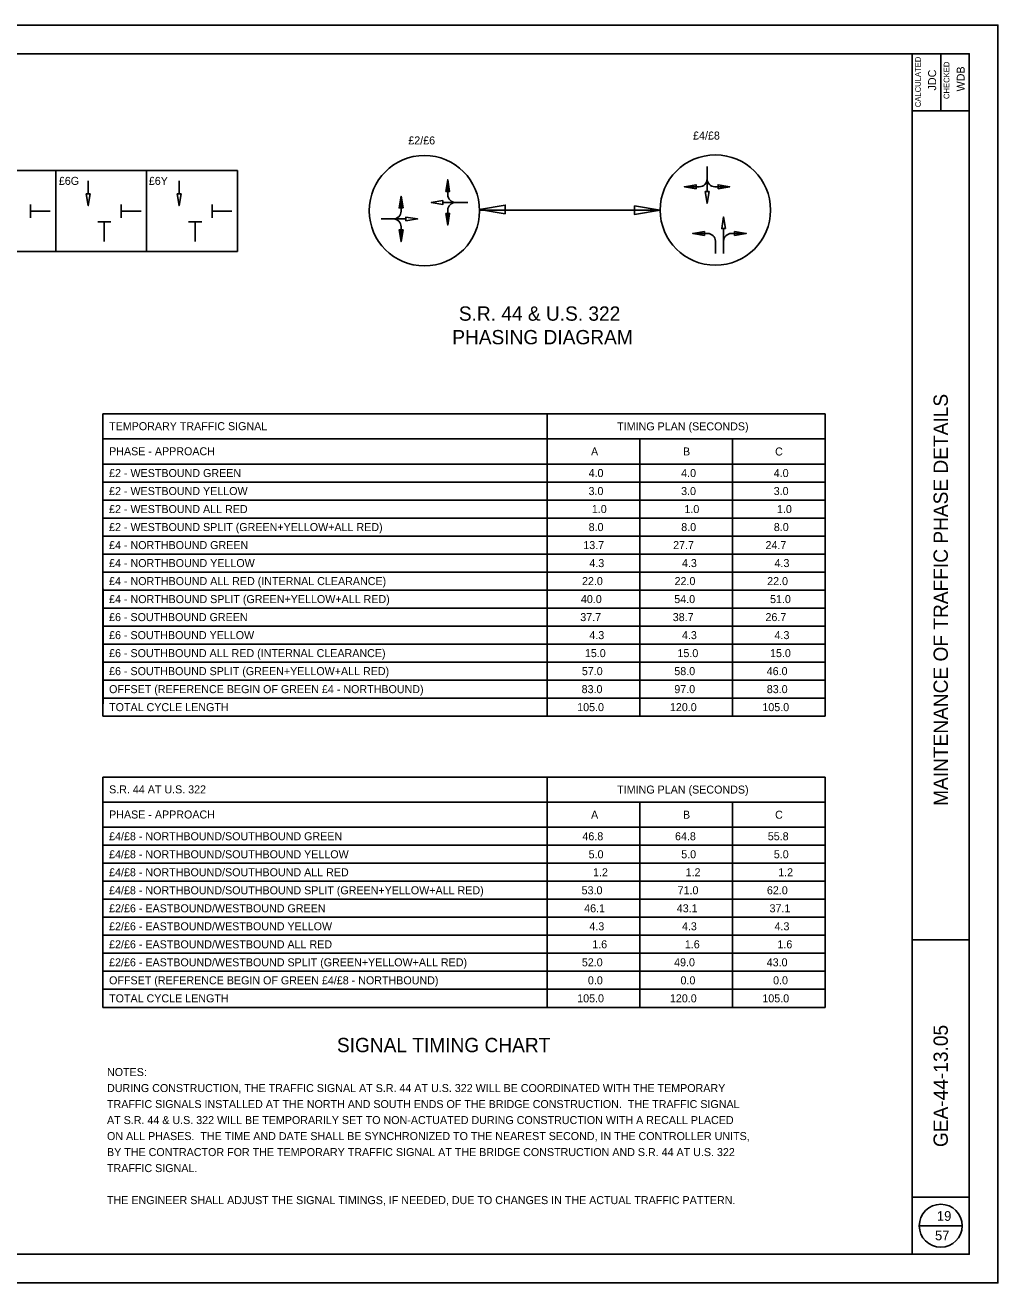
# Model space of a CAD drawing. Extents: x 2326427 to 2327107, y 683483 to 683923.
# Drawn here: x 2326766.9 to 2327107.3, y 683483.1 to 683923.1 of the extents above; entities that cross this region are included whole.
import ezdxf

# ---------------------------------------------------------------- set-up
doc = ezdxf.new("R2010")
doc.units = 0
for name, color, linetype in [('SH_Border', 7, 'Continuous'), ('SH_Cut_Line', 7, 'Continuous'), ('SH_Data', 7, 'Continuous'), ('SH_Text', 7, 'Continuous')]:
    doc.layers.add(name, color=color, linetype=linetype)

msp = doc.modelspace()

# ---------------------------------------------------------------- linework, layer by layer
at = {"layer": 'SH_Border'}
for p, q in [((2327077.3, 683493.13), (2327077.3, 683913.13)), ((2327087.3, 683913.13), (2327087.3, 683893.13)), ((2327077.3, 683893.13), (2327097.3, 683893.13)), ((2327077.3, 683603.13), (2327097.3, 683603.13)), ((2327077.3, 683513.13), (2327097.3, 683513.13))]:
    msp.add_line(p, q, dxfattribs=at)
msp.add_lwpolyline([(2326467.3, 683913.13), (2327097.3, 683913.13), (2327097.3, 683493.13), (2326467.3, 683493.13)], close=True, dxfattribs=at)
at = {"layer": 'SH_Cut_Line'}
msp.add_lwpolyline([(2326427.3, 683483.13), (2327107.3, 683483.13), (2327107.3, 683923.13), (2326427.3, 683923.13)], close=True, dxfattribs=at)
at = {"layer": 'SH_Data'}
for p, q in [((2327005.56, 683864.93), (2327005.56, 683873.63)), ((2326789, 683864.11), (2326789, 683868.72)), ((2326820.81, 683864.11), (2326820.81, 683868.72)), ((2326768.75, 683860.37), (2326768.75, 683855.76)), ((2326768.75, 683858.07), (2326775.67, 683858.07)), ((2326800.56, 683860.37), (2326800.56, 683855.76)), ((2326800.56, 683858.07), (2326807.48, 683858.07)), ((2326832.37, 683860.37), (2326832.37, 683855.76)), ((2326832.37, 683858.07), (2326839.29, 683858.07)), ((2326913.12, 683861.11), (2326921.82, 683861.11)), ((2326796.91, 683854.33), (2326792.3, 683854.33)), ((2326794.6, 683854.33), (2326794.6, 683847.41)), ((2326828.72, 683854.33), (2326824.11, 683854.33)), ((2326826.42, 683854.33), (2326826.42, 683847.41)), ((2326900.15, 683855.32), (2326891.45, 683855.32)), ((2327011.35, 683851.96), (2327011.35, 683843.26)), ((2327079.8, 683503.13), (2327094.8, 683503.13))]:
    msp.add_line(p, q, dxfattribs=at)
for points in [[(2327005.56, 683869.32), (2327005.56, 683873.63)], [(2327005.56, 683869.32), (2327005.56, 683873.63)], [(2326914.79, 683869.04), (2326914.79, 683863.83)], [(2326997.63, 683866.6), (2327002.84, 683866.6)], [(2327013.49, 683866.6), (2327008.28, 683866.6)], [(2326898.48, 683863.25), (2326898.48, 683858.04)], [(2326914.79, 683853.18), (2326914.79, 683858.39)], [(2326917.52, 683861.11), (2326921.82, 683861.11)], [(2326917.52, 683861.11), (2326921.82, 683861.11)], [(2326895.75, 683855.32), (2326891.45, 683855.32)], [(2326895.75, 683855.32), (2326891.45, 683855.32)], [(2326898.48, 683847.39), (2326898.48, 683852.6)], [(2327000.53, 683850.28), (2327005.74, 683850.28)], [(2327019.28, 683850.28), (2327014.07, 683850.28)], [(2327008.46, 683847.56), (2327008.46, 683843.26)], [(2327011.35, 683847.56), (2327011.35, 683843.26)]]:
    msp.add_lwpolyline(points, dxfattribs=at)
for points in [[(2326914.11, 683864.96), (2326915.47, 683864.96), (2326914.79, 683869.04)], [(2327001.71, 683865.92), (2327001.71, 683867.28), (2326997.63, 683866.6)], [(2327009.41, 683865.92), (2327009.41, 683867.28), (2327013.49, 683866.6)], [(2326789.68, 683864.11), (2326788.32, 683864.11), (2326789, 683860.02)], [(2326821.49, 683864.11), (2326820.13, 683864.11), (2326820.81, 683860.02)], [(2326899.16, 683859.17), (2326897.8, 683859.17), (2326898.48, 683863.25)], [(2326913.12, 683861.79), (2326913.12, 683860.43), (2326909.04, 683861.11)], [(2327004.88, 683864.93), (2327006.24, 683864.93), (2327005.56, 683860.84)], [(2326914.11, 683857.26), (2326915.47, 683857.26), (2326914.79, 683853.18)], [(2326900.15, 683854.64), (2326900.15, 683856), (2326904.24, 683855.32)], [(2327012.03, 683851.96), (2327010.67, 683851.96), (2327011.35, 683856.04)], [(2326899.16, 683851.47), (2326897.8, 683851.47), (2326898.48, 683847.39)], [(2327004.61, 683850.97), (2327004.61, 683849.6), (2327000.53, 683850.28)], [(2327015.2, 683850.97), (2327015.2, 683849.6), (2327019.28, 683850.28)]]:
    msp.add_lwpolyline(points, close=True, dxfattribs=at)
msp.add_circle((2327087.3, 683503.13), 7.5, dxfattribs=at)
for centre, start, end in [((2327002.84, 683869.32), 270, 0), ((2327008.28, 683869.32), 180, 270), ((2326917.52, 683863.83), 180, 270), ((2326895.75, 683858.04), 270, 360), ((2326917.52, 683858.39), 90, 180), ((2326895.75, 683852.6), 0, 90), ((2327005.74, 683847.56), 360, 90), ((2327014.07, 683847.56), 90, 180)]:
    msp.add_arc(centre, 2.72, start, end, dxfattribs=at)
at = {"layer": 'SH_Text'}
for p, q in [((2326491.33, 683872.24), (2326841.25, 683872.24)), ((2326777.63, 683843.89), (2326777.63, 683872.24)), ((2326809.44, 683843.89), (2326809.44, 683872.24)), ((2326841.25, 683843.89), (2326841.25, 683872.24)), ((2326925.95, 683858.44), (2326989.14, 683858.44)), ((2326491.33, 683843.89), (2326841.25, 683843.89)), ((2326794.15, 683787.16), (2327046.82, 683787.16)), ((2326794.15, 683681.39), (2326794.15, 683787.16)), ((2326949.62, 683787.16), (2326949.62, 683681.39)), ((2327046.82, 683787.16), (2327046.82, 683681.39)), ((2326794.15, 683778.37), (2327046.82, 683778.37)), ((2326982.02, 683778.37), (2326982.02, 683681.39)), ((2327014.42, 683778.37), (2327014.42, 683681.39)), ((2326794.15, 683769.59), (2327046.82, 683769.59)), ((2326982.02, 683769.59), (2326982.02, 683681.39)), ((2327014.42, 683769.59), (2327014.42, 683681.39)), ((2327046.82, 683769.59), (2327046.82, 683681.39)), ((2326794.15, 683763.29), (2327046.82, 683763.29)), ((2326794.15, 683756.99), (2327046.82, 683756.99)), ((2326794.15, 683750.69), (2327046.82, 683750.69)), ((2326794.15, 683744.39), (2327046.82, 683744.39)), ((2326794.15, 683738.09), (2327046.82, 683738.09)), ((2326794.15, 683731.79), (2327046.82, 683731.79)), ((2326794.15, 683725.49), (2327046.82, 683725.49)), ((2326794.21, 683725.97), (2326794.21, 683685.69)), ((2326794.15, 683719.19), (2327046.82, 683719.19)), ((2326794.15, 683712.89), (2327046.82, 683712.89)), ((2326794.15, 683706.59), (2327046.82, 683706.59)), ((2326794.15, 683700.29), (2327046.82, 683700.29)), ((2326794.15, 683693.99), (2327046.82, 683693.99)), ((2326794.15, 683687.69), (2327046.82, 683687.69)), ((2326794.15, 683681.39), (2327046.82, 683681.39)), ((2326794.15, 683660.09), (2327046.82, 683660.09)), ((2326794.15, 683579.52), (2326794.15, 683660.09)), ((2326949.62, 683660.09), (2326949.62, 683579.52)), ((2327046.82, 683660.09), (2327046.82, 683579.52)), ((2326794.15, 683651.3), (2327046.82, 683651.3)), ((2326982.02, 683651.3), (2326982.02, 683579.52)), ((2327014.42, 683651.3), (2327014.42, 683579.52)), ((2326794.15, 683642.52), (2327046.82, 683642.52)), ((2326982.02, 683642.52), (2326982.02, 683579.52)), ((2327014.42, 683642.52), (2327014.42, 683579.52)), ((2327046.82, 683642.52), (2327046.82, 683579.52)), ((2326794.15, 683636.22), (2327046.82, 683636.22)), ((2326794.15, 683629.92), (2327046.82, 683629.92)), ((2326794.15, 683623.62), (2327046.82, 683623.62)), ((2326794.15, 683617.32), (2327046.82, 683617.32)), ((2326794.15, 683611.02), (2327046.82, 683611.02)), ((2326794.15, 683604.72), (2327046.82, 683604.72)), ((2326794.15, 683598.42), (2327046.82, 683598.42)), ((2326794.15, 683592.12), (2327046.82, 683592.12)), ((2326794.15, 683585.82), (2327046.82, 683585.82)), ((2326794.15, 683579.52), (2327046.82, 683579.52))]:
    msp.add_line(p, q, dxfattribs=at)
for points in [[(2326934.95, 683857.17), (2326934.95, 683860.17), (2326925.95, 683858.67)], [(2326980.14, 683859.94), (2326980.14, 683856.94), (2326989.14, 683858.44)]]:
    msp.add_lwpolyline(points, close=True, dxfattribs=at)
for centre in [(2326906.64, 683858.22), (2327008.46, 683858.44)]:
    msp.add_circle(centre, 19.31, dxfattribs=at)

# ---------------------------------------------------------------- texts
at = {"layer": 'SH_Data'}
for s, height, p in [('CALCULATED', 2, (2327080.35, 683894.43)), ('CHECKED', 2, (2327090.35, 683897.29)), ('JDC', 2.8, (2327085.7, 683900.29)), ('WDB', 2.8, (2327095.7, 683899.95)), ('MAINTENANCE OF TRAFFIC PHASE DETAILS', 5, (2327089.8, 683649.99)), ('GEA-44-13.05', 5, (2327089.8, 683530.64))]:
    msp.add_text(s, height=height, rotation=90, dxfattribs=at).set_placement(p)
for s, p in [('19', (2327085.97, 683504.83)), ('57', (2327085.31, 683498.03))]:
    msp.add_text(s, height=3.4, dxfattribs=at).set_placement(p)
at = {"layer": 'SH_Text'}
for s, p in [('£2/£6', (2326901.01, 683881.41)), ('£4/£8', (2327000.65, 683883.11)), ('£6G', (2326778.72, 683867.25)), ('£6Y', (2326810.2, 683867.25)), ('TEMPORARY TRAFFIC SIGNAL', (2326796.3, 683781.44)), ('TIMING PLAN (SECONDS)', (2326974.1, 683781.37)), ('PHASE - APPROACH', (2326796.3, 683772.66)), ('A', (2326964.95, 683772.58)), ('B', (2326997.13, 683772.58)), ('C', (2327029.36, 683772.58)), ('£2 - WESTBOUND GREEN', (2326796.3, 683765.04)), ('4.0', (2326964.09, 683765.04)), ('4.0', (2326996.49, 683765.04)), ('4.0', (2327028.89, 683765.04)), ('£2 - WESTBOUND YELLOW', (2326796.3, 683758.74)), ('3.0', (2326964.07, 683758.74)), ('3.0', (2326996.47, 683758.74)), ('3.0', (2327028.87, 683758.74)), ('£2 - WESTBOUND ALL RED', (2326796.3, 683752.44)), ('1.0', (2326965.22, 683752.44)), ('1.0', (2326997.62, 683752.44)), ('1.0', (2327030.02, 683752.44)), ('£2 - WESTBOUND SPLIT (GREEN+YELLOW+ALL RED)', (2326796.3, 683746.14)), ('8.0', (2326964.11, 683746.14)), ('8.0', (2326996.51, 683746.14)), ('8.0', (2327028.91, 683746.14)), ('£4 - NORTHBOUND GREEN', (2326796.3, 683739.84)), ('13.7', (2326962.24, 683739.84)), ('27.7', (2326993.67, 683739.84)), ('24.7', (2327026, 683739.84)), ('£4 - NORTHBOUND YELLOW', (2326796.3, 683733.54)), ('4.3', (2326964.36, 683733.54)), ('4.3', (2326996.76, 683733.54)), ('4.3', (2327029.16, 683733.54)), ('£4 - NORTHBOUND ALL RED (INTERNAL CLEARANCE)', (2326796.3, 683727.24)), ('22.0', (2326961.78, 683727.24)), ('22.0', (2326994.18, 683727.24)), ('22.0', (2327026.58, 683727.24)), ('£4 - NORTHBOUND SPLIT (GREEN+YELLOW+ALL RED)', (2326796.3, 683720.94)), ('40.0', (2326961.4, 683720.94)), ('54.0', (2326994.07, 683720.94)), ('51.0', (2327027.59, 683720.94)), ('£6 - SOUTHBOUND GREEN', (2326796.3, 683714.64)), ('37.7', (2326961.18, 683714.64)), ('38.7', (2326993.54, 683714.64)), ('26.7', (2327025.98, 683714.64)), ('£6 - SOUTHBOUND YELLOW', (2326796.3, 683708.34)), ('4.3', (2326964.36, 683708.34)), ('4.3', (2326996.76, 683708.34)), ('4.3', (2327029.16, 683708.34)), ('£6 - SOUTHBOUND ALL RED (INTERNAL CLEARANCE)', (2326796.3, 683702.04)), ('15.0', (2326962.79, 683702.04)), ('15.0', (2326995.19, 683702.04)), ('15.0', (2327027.59, 683702.04)), ('£6 - SOUTHBOUND SPLIT (GREEN+YELLOW+ALL RED)', (2326796.3, 683695.74)), ('57.0', (2326961.73, 683695.74)), ('58.0', (2326994.09, 683695.74)), ('46.0', (2327026.42, 683695.74)), ('OFFSET (REFERENCE BEGIN OF GREEN £4 - NORTHBOUND)', (2326796.3, 683689.44)), ('83.0', (2326961.65, 683689.44)), ('97.0', (2326994.09, 683689.44)), ('83.0', (2327026.45, 683689.44)), ('TOTAL CYCLE LENGTH', (2326796.3, 683683.14)), ('105.0', (2326960.1, 683683.14)), ('120.0', (2326992.55, 683683.14)), ('105.0', (2327024.9, 683683.14)), ('S.R. 44 AT U.S. 322', (2326796.3, 683654.37)), ('TIMING PLAN (SECONDS)', (2326974.1, 683654.3)), ('PHASE - APPROACH', (2326796.3, 683645.59)), ('A', (2326964.95, 683645.51)), ('B', (2326997.13, 683645.51)), ('C', (2327029.36, 683645.51)), ('£4/£8 - NORTHBOUND/SOUTHBOUND GREEN', (2326796.3, 683637.97)), ('46.8', (2326961.93, 683637.97)), ('64.8', (2326994.33, 683637.97)), ('55.8', (2327026.8, 683637.97)), ('£4/£8 - NORTHBOUND/SOUTHBOUND YELLOW', (2326796.3, 683631.67)), ('5.0', (2326964.11, 683631.67)), ('5.0', (2326996.51, 683631.67)), ('5.0', (2327028.91, 683631.67)), ('£4/£8 - NORTHBOUND/SOUTHBOUND ALL RED', (2326796.3, 683625.37)), ('1.2', (2326965.64, 683625.37)), ('1.2', (2326998.04, 683625.37)), ('1.2', (2327030.44, 683625.37)), ('£4/£8 - NORTHBOUND/SOUTHBOUND SPLIT (GREEN+YELLOW+ALL RED)', (2326796.3, 683619.07)), ('53.0', (2326961.65, 683619.07)), ('71.0', (2326995.24, 683619.07)), ('62.0', (2327026.49, 683619.07)), ('£2/£6 - EASTBOUND/WESTBOUND GREEN', (2326796.3, 683612.77)), ('46.1', (2326962.55, 683612.77)), ('43.1', (2326994.95, 683612.77)), ('37.1', (2327027.41, 683612.77)), ('£2/£6 - EASTBOUND/WESTBOUND YELLOW', (2326796.3, 683606.47)), ('4.3', (2326964.36, 683606.47)), ('4.3', (2326996.76, 683606.47)), ('4.3', (2327029.16, 683606.47)), ('£2/£6 - EASTBOUND/WESTBOUND ALL RED', (2326796.3, 683600.17)), ('1.6', (2326965.37, 683600.17)), ('1.6', (2326997.77, 683600.17)), ('1.6', (2327030.17, 683600.17)), ('£2/£6 - EASTBOUND/WESTBOUND SPLIT (GREEN+YELLOW+ALL RED)', (2326796.3, 683593.87)), ('52.0', (2326961.73, 683593.87)), ('49.0', (2326994.02, 683593.87)), ('43.0', (2327026.42, 683593.87)), ('OFFSET (REFERENCE BEGIN OF GREEN £4/£8 - NORTHBOUND)', (2326796.3, 683587.57)), ('0.0', (2326963.85, 683587.57)), ('0.0', (2326996.25, 683587.57)), ('0.0', (2327028.65, 683587.57)), ('TOTAL CYCLE LENGTH', (2326796.3, 683581.27)), ('105.0', (2326960.1, 683581.27)), ('120.0', (2326992.55, 683581.27)), ('105.0', (2327024.9, 683581.27)), ('NOTES:', (2326795.57, 683555.48)), ('DURING CONSTRUCTION, THE TRAFFIC SIGNAL AT S.R. 44 AT U.S. 322 WILL BE COORDINATED WITH THE TEMPORARY', (2326795.57, 683549.88)), ('TRAFFIC SIGNALS INSTALLED AT THE NORTH AND SOUTH ENDS OF THE BRIDGE CONSTRUCTION.  THE TRAFFIC SIGNAL', (2326795.57, 683544.28)), ('AT S.R. 44 & U.S. 322 WILL BE TEMPORARILY SET TO NON-ACTUATED DURING CONSTRUCTION WITH A RECALL PLACED', (2326795.57, 683538.68)), ('ON ALL PHASES.  THE TIME AND DATE SHALL BE SYNCHRONIZED TO THE NEAREST SECOND, IN THE CONTROLLER UNITS,', (2326795.57, 683533.08)), ('BY THE CONTRACTOR FOR THE TEMPORARY TRAFFIC SIGNAL AT THE BRIDGE CONSTRUCTION AND S.R. 44 AT U.S. 322', (2326795.57, 683527.48)), ('TRAFFIC SIGNAL.', (2326795.57, 683521.88)), ('THE ENGINEER SHALL ADJUST THE SIGNAL TIMINGS, IF NEEDED, DUE TO CHANGES IN THE ACTUAL TRAFFIC PATTERN.', (2326795.57, 683510.68))]:
    msp.add_text(s, height=2.8, dxfattribs=at).set_placement(p)
for s, p in [('S.R. 44 & U.S. 322', (2326918.69, 683819.73)), ('PHASING DIAGRAM', (2326916.38, 683811.48)), ('SIGNAL TIMING CHART', (2326876.03, 683563.83))]:
    msp.add_text(s, height=5, rotation=359.9999, dxfattribs=at).set_placement(p)

doc.saveas('drawing.dxf')
